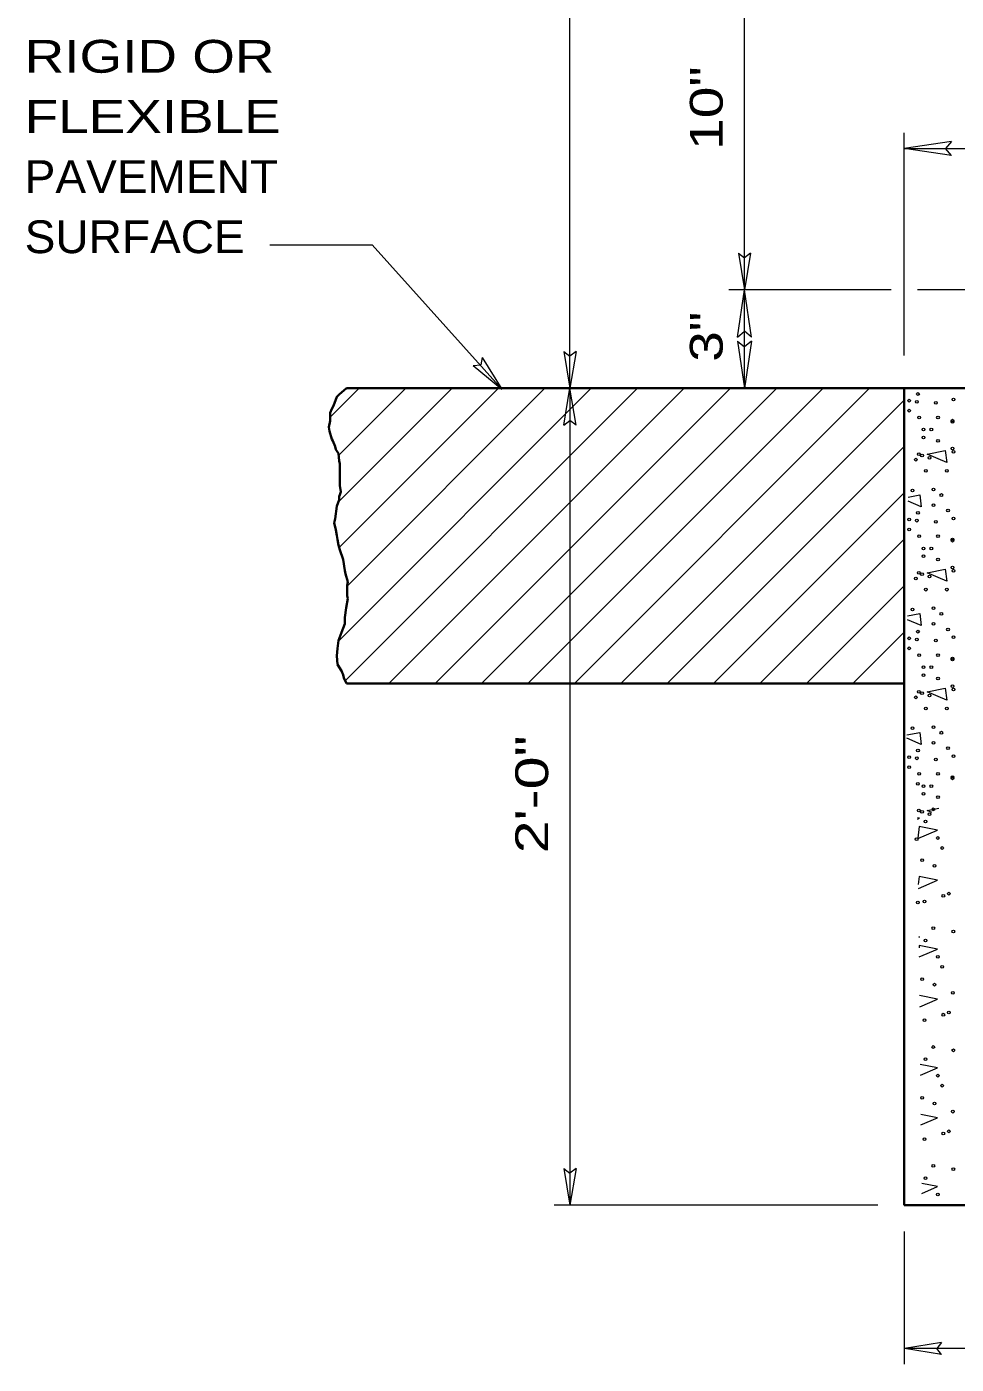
# Model space of a CAD drawing. Extents: x -16.43 to -9.36, y -8.57 to 1.26.
# Drawn here: x -16.272 to -14.571, y -3.289 to -0.843 of the extents above; entities that cross this region are included whole.
import ezdxf
from ezdxf.enums import TextEntityAlignment as Align

# ---------------------------------------------------------------- set-up
doc = ezdxf.new("R2010")
doc.units = 0
doc.header["$LTSCALE"] = 0.024
for name, color, linetype, lineweight in [('1', 7, 'Continuous', 35), ('10', 7, 'Continuous', 13), ('12', 7, 'Continuous', 53), ('6', 7, 'Continuous', 13)]:
    doc.layers.add(name, color=color, linetype=linetype, lineweight=lineweight)

msp = doc.modelspace()

# ---------------------------------------------------------------- linework, layer by layer
at = {"layer": '1'}
for p, q in [((-14.66667, -1.504), (-15.68667, -1.504)), ((-14.66667, -1.504), (-14.66667, -2.99817)), ((-14.2765, -1.504), (-14.66667, -1.504)), ((-15.68667, -2.044), (-14.66667, -2.044)), ((-14.66667, -2.99817), (-12.69033, -2.99817))]:
    msp.add_line(p, q, dxfattribs=at)
at = {"layer": '10'}
for p, q in [((-15.278, -1.504), (-15.278, 0.53633)), ((-14.66667, -1.444), (-14.66667, -1.03667)), ((-14.58017, -1.05283), (-14.66667, -1.0655)), ((-14.66667, -1.0655), (-14.2765, -1.0655)), ((-14.58017, -1.078), (-14.66667, -1.0655)), ((-14.58017, -1.05283), (-14.591, -1.0655)), ((-14.58017, -1.078), (-14.591, -1.0655)), ((-15.82667, -1.24183), (-15.63967, -1.24183)), ((-15.63967, -1.24183), (-15.40267, -1.5055)), ((-14.96983, -1.25667), (-14.95867, -1.324)), ((-14.96983, -1.25667), (-14.95867, -1.26517)), ((-14.9475, -1.25667), (-14.95867, -1.324)), ((-14.9475, -1.25667), (-14.95867, -1.26517)), ((-14.69067, -1.324), (-14.9875, -1.324)), ((-14.97133, -1.41033), (-14.95867, -1.324)), ((-14.94617, -1.41033), (-14.95867, -1.324)), ((-14.3245, -1.324), (-14.6425, -1.324)), ((-14.97133, -1.41033), (-14.95867, -1.3995)), ((-14.97133, -1.4175), (-14.95867, -1.504)), ((-14.97133, -1.4175), (-14.95867, -1.42833)), ((-14.94617, -1.41033), (-14.95867, -1.3995)), ((-14.94617, -1.4175), (-14.95867, -1.504)), ((-14.94617, -1.4175), (-14.95867, -1.42833)), ((-15.28917, -1.43683), (-15.278, -1.504)), ((-15.28917, -1.43683), (-15.278, -1.44517)), ((-15.26683, -1.43683), (-15.278, -1.504)), ((-15.26683, -1.43683), (-15.278, -1.44517)), ((-15.45533, -1.462), (-15.44133, -1.46117)), ((-15.45533, -1.462), (-15.40267, -1.5055)), ((-15.43833, -1.44733), (-15.44133, -1.46117)), ((-15.43833, -1.44733), (-15.40267, -1.5055)), ((-15.28917, -1.57117), (-15.278, -1.504)), ((-15.278, -1.504), (-15.278, -2.99817)), ((-15.26683, -1.57117), (-15.278, -1.504)), ((-15.28917, -1.57117), (-15.278, -1.56283)), ((-15.26683, -1.57117), (-15.278, -1.56283)), ((-15.28917, -2.931), (-15.278, -2.99817)), ((-15.28917, -2.931), (-15.278, -2.93933)), ((-15.26683, -2.931), (-15.278, -2.99817)), ((-15.26683, -2.931), (-15.278, -2.93933)), ((-14.71467, -2.99817), (-15.30683, -2.99817)), ((-14.66667, -3.04617), (-14.66667, -3.289)), ((-14.5985, -3.249), (-14.66583, -3.26017)), ((-14.5985, -3.249), (-14.607, -3.26017)), ((-12.69017, -3.26017), (-14.66583, -3.26017)), ((-14.5985, -3.27133), (-14.66583, -3.26017)), ((-14.5985, -3.27133), (-14.607, -3.26017))]:
    msp.add_line(p, q, dxfattribs=at)
msp.add_lwpolyline([(-14.95867, -1.504), (-14.95867, -1.324), (-14.95867, -0.66783), (-14.95867, 0.53633)], dxfattribs=at)
at = {"layer": '10', "lineweight": 35}
msp.add_lwpolyline([(-15.68667, -1.504), (-15.70033, -1.5155), (-15.70467, -1.51983), (-15.7105, -1.53583), (-15.71333, -1.54167), (-15.71633, -1.549), (-15.71633, -1.5635), (-15.71917, -1.57517), (-15.71767, -1.5825), (-15.71333, -1.597), (-15.71183, -1.6), (-15.7075, -1.61017), (-15.706, -1.616), (-15.70167, -1.62333), (-15.70033, -1.63633), (-15.69883, -1.64217), (-15.69883, -1.65533), (-15.69883, -1.66267), (-15.69883, -1.67417), (-15.69883, -1.6815), (-15.69733, -1.69317), (-15.69883, -1.699), (-15.70033, -1.70183), (-15.70033, -1.70767), (-15.70467, -1.71933), (-15.7075, -1.74267), (-15.709, -1.74983), (-15.706, -1.763), (-15.70467, -1.77317), (-15.70317, -1.7805), (-15.70167, -1.79067), (-15.69883, -1.79933), (-15.693, -1.81683), (-15.69, -1.83717), (-15.68867, -1.843), (-15.68417, -1.85767), (-15.68567, -1.86483), (-15.68567, -1.88367), (-15.68417, -1.88817), (-15.68717, -1.9055), (-15.69, -1.923), (-15.69, -1.93467), (-15.69583, -1.95067), (-15.70167, -1.96533), (-15.70317, -1.97983), (-15.70467, -1.993), (-15.70317, -2.00883), (-15.69583, -2.0205), (-15.693, -2.02783), (-15.6915, -2.03367), (-15.68667, -2.044)], dxfattribs=at)
at = {"layer": '6'}
for p, q in [((-15.71633, -1.55683), (-15.6635, -1.504)), ((-15.702, -1.71233), (-15.49367, -1.504)), ((-15.70183, -1.96683), (-15.239, -1.504)), ((-15.70133, -1.62683), (-15.5785, -1.504)), ((-15.70017, -1.79533), (-15.40883, -1.504)), ((-15.68917, -2.03883), (-15.15417, -1.504)), ((-15.68567, -1.86567), (-15.324, -1.504)), ((-15.60933, -2.044), (-15.06933, -1.504)), ((-15.5245, -2.044), (-14.9845, -1.504)), ((-15.43967, -2.044), (-14.89967, -1.504)), ((-15.35483, -2.044), (-14.81467, -1.504)), ((-15.27, -2.044), (-14.72983, -1.504)), ((-15.185, -2.044), (-14.66667, -1.5255)), ((-15.10017, -2.044), (-14.66667, -1.6105)), ((-15.01533, -2.044), (-14.66667, -1.69533)), ((-14.9305, -2.044), (-14.66667, -1.78017)), ((-14.8455, -2.044), (-14.66667, -1.865)), ((-14.76083, -2.044), (-14.66667, -1.94983)), ((-14.62467, -2.27633), (-14.6035, -2.27217)), ((-14.6385, -2.29017), (-14.64217, -2.2895)), ((-14.64217, -2.29183), (-14.6385, -2.29017)), ((-14.61633, -2.27967), (-14.62467, -2.27633)), ((-14.64167, -2.3275), (-14.60583, -2.31217)), ((-14.64067, -2.41867), (-14.60583, -2.40367)), ((-14.6385, -2.5075), (-14.63967, -2.50733)), ((-14.63967, -2.50817), (-14.6385, -2.5075)), ((-14.63933, -2.54383), (-14.60583, -2.5295)), ((-14.60583, -2.621), (-14.6385, -2.61467)), ((-14.63833, -2.635), (-14.60583, -2.621)), ((-14.60583, -2.74683), (-14.63717, -2.74067)), ((-14.637, -2.76017), (-14.60583, -2.74683)), ((-14.60583, -2.8385), (-14.63617, -2.8325)), ((-14.636, -2.85133), (-14.60583, -2.8385)), ((-14.60583, -2.96417), (-14.63467, -2.9585)), ((-14.6345, -2.9765), (-14.60583, -2.96417))]:
    msp.add_line(p, q, dxfattribs=at)
for points in [[(-14.62467, -1.62417), (-14.5915, -1.61767), (-14.58867, -1.63967)], [(-14.62467, -1.8415), (-14.5915, -1.835), (-14.58867, -1.857)], [(-14.62467, -2.05883), (-14.5915, -2.05233), (-14.58867, -2.07433)]]:
    msp.add_lwpolyline(points, close=True, dxfattribs=at)
for points in [[(-14.65917, -1.70283), (-14.63833, -1.69867), (-14.6355, -1.7205), (-14.65933, -1.71033)], [(-14.6605, -1.92033), (-14.63833, -1.916), (-14.6355, -1.938), (-14.6605, -1.92717)], [(-14.66183, -2.138), (-14.63833, -2.13333), (-14.6355, -2.15533), (-14.66183, -2.144)], [(-14.60583, -2.31217), (-14.639, -2.30567), (-14.64167, -2.32683)], [(-14.60583, -2.40367), (-14.639, -2.39717), (-14.64083, -2.4115)], [(-14.60583, -2.5295), (-14.639, -2.523), (-14.6395, -2.5275)]]:
    msp.add_lwpolyline(points, dxfattribs=at)
for centre in [(-14.64146, -1.51437), (-14.65774, -1.52657), (-14.6435, -1.52861), (-14.60889, -1.53065), (-14.57633, -1.52453), (-14.65774, -1.54489), (-14.63942, -1.55714), (-14.60481, -1.55714), (-14.57833, -1.56322), (-14.57833, -1.56526), (-14.6313, -1.5795), (-14.61702, -1.5795), (-14.6313, -1.59378), (-14.60481, -1.59986), (-14.57833, -1.61415), (-14.64554, -1.63447), (-14.63966, -1.62423), (-14.63402, -1.62667), (-14.62038, -1.63103), (-14.57633, -1.62023), (-14.62722, -1.65483), (-14.58853, -1.65483), (-14.61298, -1.68896), (-14.65166, -1.691), (-14.59869, -1.69916), (-14.64146, -1.73172), (-14.61298, -1.71748), (-14.58649, -1.72764), (-14.65774, -1.74393), (-14.65774, -1.76225), (-14.6435, -1.74597), (-14.60889, -1.74801), (-14.57633, -1.74189), (-14.63942, -1.77449), (-14.60481, -1.77449), (-14.57833, -1.78057), (-14.57833, -1.78261), (-14.6313, -1.79686), (-14.6313, -1.81114), (-14.61702, -1.79686), (-14.60481, -1.81722), (-14.57833, -1.8315), (-14.64554, -1.85182), (-14.63966, -1.84158), (-14.63402, -1.84402), (-14.62038, -1.84838), (-14.57633, -1.83758), (-14.62722, -1.87219), (-14.58853, -1.87219), (-14.65166, -1.90835), (-14.61298, -1.90631), (-14.61298, -1.93484), (-14.59869, -1.91651), (-14.64146, -1.94908), (-14.58649, -1.945), (-14.57633, -1.95924), (-14.65774, -1.96128), (-14.65774, -1.9796), (-14.6435, -1.96332), (-14.60889, -1.96536), (-14.63942, -1.99185), (-14.60481, -1.99185), (-14.57833, -1.99793), (-14.57833, -1.99997), (-14.6313, -2.01421), (-14.6313, -2.02849), (-14.61702, -2.01421), (-14.60481, -2.03457), (-14.57833, -2.04886), (-14.57633, -2.05494), (-14.64554, -2.06918), (-14.63966, -2.05894), (-14.63402, -2.06138), (-14.62038, -2.06574), (-14.62722, -2.08954), (-14.58853, -2.08954), (-14.65166, -2.12571), (-14.61298, -2.12367), (-14.61298, -2.15219), (-14.59869, -2.13387), (-14.65774, -2.17864), (-14.64146, -2.16643), (-14.58649, -2.16235), (-14.57633, -2.1766), (-14.65774, -2.19696), (-14.6435, -2.18068), (-14.60889, -2.18272), (-14.64188, -2.2272), (-14.63942, -2.2092), (-14.60481, -2.2092), (-14.57833, -2.21528), (-14.57833, -2.21732), (-14.6313, -2.23156), (-14.6313, -2.24585), (-14.61702, -2.23156), (-14.60481, -2.25193), (-14.63966, -2.27629), (-14.6134, -2.27401), (-14.63402, -2.27873), (-14.62764, -2.29641), (-14.62038, -2.28309), (-14.60524, -2.32646), (-14.64392, -2.3285), (-14.59712, -2.34478), (-14.63376, -2.36719), (-14.61136, -2.37735), (-14.64188, -2.44456), (-14.62968, -2.44252), (-14.59508, -2.43232), (-14.58487, -2.42828), (-14.6134, -2.49137), (-14.57675, -2.49749), (-14.62764, -2.51377), (-14.60524, -2.54381), (-14.59712, -2.56214), (-14.63376, -2.58454), (-14.61136, -2.5947), (-14.57747, -2.60959), (-14.62968, -2.65987), (-14.59508, -2.64967), (-14.58487, -2.64563), (-14.6134, -2.70872), (-14.57675, -2.71484), (-14.62764, -2.73112), (-14.60524, -2.76117), (-14.59712, -2.77949), (-14.63376, -2.8019), (-14.61136, -2.81206), (-14.57747, -2.82694), (-14.58487, -2.86299), (-14.62968, -2.87723), (-14.59508, -2.86703), (-14.6134, -2.92608), (-14.57675, -2.9322), (-14.62764, -2.94848), (-14.60524, -2.97852)]:
    msp.add_circle(centre, 0.00252, dxfattribs=at)

# ---------------------------------------------------------------- texts
at = {"layer": '12'}
for s, width, p in [('RIGID OR', 1.25, (-16.27542, -0.92675)), ('FLEXIBLE', 1.25, (-16.27542, -1.03675)), ('PAVEMENT', 1.05, (-16.27542, -1.14675)), ('SURFACE', 1.05, (-16.27542, -1.25675))]:
    msp.add_text(s, height=0.06001, dxfattribs=dict(at, width=width)).set_placement(p)
for s, width, p in [('10"', 1.3, (-14.99867, -0.99158)), ('3"', 1.25, (-14.99867, -1.40967)), ('2\'-0"', 1.35, (-15.31792, -2.24675))]:
    msp.add_text(s, height=0.06001, rotation=90, dxfattribs=dict(at, width=width)).set_placement(p, align=Align.CENTER)

doc.saveas('drawing.dxf')
